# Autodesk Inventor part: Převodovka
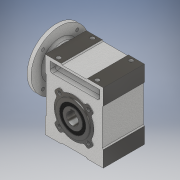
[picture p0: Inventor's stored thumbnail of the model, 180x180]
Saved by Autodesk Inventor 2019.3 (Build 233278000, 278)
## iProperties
Created: 2019-02
Part Number: Převodovka
Material: Hliník 6061-AHC
Document SubType Name: Modeling
Designer: B-hon
Density: 2.7 g/cm^3
Appearance: Hliník – litý
Author: B-hon
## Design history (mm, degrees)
sketch "Náčrt1"
  geometry: L1 (-60, 84)-(60, -60); L2 (60, 84)-(-60, -60); L3 (-27, -58)-(27, -58); L4 (-27, 82)-(27, 82); L5 (-27, 82)-(-27, 84); L6 (27, 82)-(27, 84); L7 (-27, -58)-(-27, -60); L8 (27, -58)-(27, -60); L9 (60, -60)-(27, -60); L10 (-27, -60)-(-60, -60); L11 (-60, 84)-(-27, 84); L12 (27, 84)-(60, 84); L13 (-58, 51)-(-58, -27); L14 (-58, 51)-(-60, 51); L15 (-58, -27)-(-60, -27); L16 (-60, -60)-(-60, -27); L17 (-60, 51)-(-60, 84); L18 (58, 51)-(58, -27); L19 (58, 51)-(60, 51); L20 (58, -27)-(60, -27); L21 (60, 84)-(60, 51); L22 (60, -27)-(60, -60); L23 (-4, 15.8)-(4, 15.8); L24 (-4, 15.8)-(-4, 11.843); L25 (4, 15.8)-(4, 11.843); A1 r 12.5 centre (0, 0) between (-4, 11.843) and (4, 11.843); 10 further points
  constraints: 50 end point, 10 parallel, 10 perpendicular, 7 midpoint, 6 horizontal, 4 vertical, 4 vertical alignment, 2 horizontal alignment, 2 point on circle, 2 point on line, 1 centre point, 1 coincident
  dimensions: "d0" = 144 distance of L2.end L1.start; "d1" = 120 distance of L1.end L2.end; "d2" = 25 diameter of A1; "d4" = 54 distance of L3.start L3.end; "d6" = 54 distance of L4.start L4.end; "d8" = 78 distance of L13.start L13.end; "d10" = 78 distance of L18.start L18.end; "d12" = 8 distance of L23.start L23.end; "d13" = 15.8 distance from line of point (0, 0) L23
extrude "Vysunutí1" new body sketch "Náčrt1" stored distance "d14" = 85; taper "d15" = 0 deg
sketch "Náčrt2"
  geometry: L1 (4, 15.8)-(4, 11.843) reference; L2 (-4, 15.8)-(4, 15.8) reference; L3 (-4, 11.843)-(-4, 15.8) reference; C1 r 35 at (0, 0); A1 r 12.5 centre (0, 0) between (-4, 11.843) and (4, 11.843) reference; 1 further point
  constraints: 1 centre point, 1 coincident
  dimensions: "d16" = 70 diameter of C1
extrude "Vysunutí2" join sketch "Náčrt2" distance "d18" = 3.5; taper "d19" = 0 deg
sketch "Náčrt3"
  geometry: C1 r 27.5 at (0, 0); C2 r 20 at (0, 0); 1 further point
  constraints: 2 centre point, 2 coincident
  dimensions: "d20" = 55 diameter of C1; "d21" = 40 diameter of C2
extrude "Vysunutí3" cut sketch "Náčrt3" distance "d22" = 1; taper "d23" = 0 deg
sketch "Náčrt4" dims "d29" = 85
  geometry: L1 (21.739, 34.467)-(28.234, 40.962); L2 (34.467, 21.739)-(40.962, 28.234); L3 (27, 82)-(-27, 82) reference; L4 (0, 40.75)-(0, 35); L5 (35, 0)-(40.75, 0); C1 r 3 at (30.052, 30.052); A1 r 35 centre (0, 0) between (35, 0) and (0, 35); A2 r 49.75 centre (0, 0) between (40.962, 28.234) and (28.234, 40.962); A3 r 35 centre (0, 0) between (0, 35) and (35, 0) reference; A4 r 40.75 centre (0, 0) between (40.75, 0) and (34.467, 21.739); A5 r 40.75 centre (0, 0) between (21.739, 34.467) and (0, 40.75); 2 further points
  constraints: 9 point on circle, 8 end point, 5 centre point, 4 coincident, 1 parallel, 1 vertical, 3 other
  dimensions: "d25" = 99.5 diameter of A2; "d26" = 45 deg angle of L3 L1; "d27" = 18 distance between parallel lines of L2 L1; "d28" = 9 distance from line of point (0, 0) L1; "d30" = 6 diameter of C1; "d31" = 9 distance from line of C1.centre L1
extrude "Vysunutí4" join sketch "Náčrt4" distance "d33" = 1; taper "d34" = 0 deg
fillet "Zaoblení1" dims "d35" = 5
pattern_circular "Kruhové pole1" dims angle "d37" = 360 deg
chamfer "Zkosení1" distance "d39" = 2; stored, may be unused: second distance "d40" = 2, angle "d41" = 45 deg
sketch "Náčrt5"
  geometry: C1 r 3 at (-30.052, 30.052) reference; C2 r 3 at (30.052, 30.052) reference; C3 r 3 at (30.052, -30.052) reference; C4 r 3 at (-30.052, -30.052) reference; 5 further points
  constraints: 4 coincident
hole "Díra1" sketch "Náčrt5" at (-30.052, 30.052), (30.052, 30.052), (30.052, -30.052), (-30.052, -30.052) diameter "d42" = 6.647; stored, may be unused: countersink angle "d46" = 90 deg, drill point angle "d48" = 118 deg; dims "d43" = 16, "d44" = 8, "d45" = 2, "d47" = 22.2
mirror "Zrcadlit1"
fillet "Zaoblení2" dims "d49" = 5
mirror "Zrcadlit2"
sketch "Náčrt6"
  geometry: C1 r 3 at (-30.052, 30.052) reference; C2 r 3 at (30.052, 30.052) reference; C3 r 3 at (30.052, -30.052) reference; C4 r 3 at (-30.052, -30.052) reference; 5 further points
  constraints: 4 coincident
hole "Díra2" sketch "Náčrt6" at (-30.052, 30.052), (30.052, 30.052), (30.052, -30.052), (-30.052, -30.052) diameter "d50" = 6.647; stored, may be unused: countersink angle "d54" = 90 deg, drill point angle "d56" = 118 deg; dims "d51" = 16, "d52" = 8, "d53" = 2, "d55" = 22.2
sketch "Náčrt7"
  geometry: L1 (0, 0)-(85, 0) reference; C1 r 33.5 at (42.5, -36.5); 1 further point
  constraints: 1 centre point, 1 vertical alignment
  dimensions: "d57" = 67 diameter of C1; "d58" = 36.5 distance from line of C1.centre L1
extrude "Vysunutí5" join sketch "Náčrt7" distance "d59" = 4; taper "d61" = 0 deg; dims "d60" = 2, "d62" = 0
node "Pracovní rovina1"
sketch "Náčrt8"
  geometry: C1 r 34.7 at (0, 0); 1 further point
  constraints: 1 centre point
  dimensions: "d64" = 69.4 diameter of C1
sketch "Náčrt9"
  geometry: C1 r 33.5 at (0, 0) reference; 1 further point
  node "Promítnutá smyčka1"
feature "Šablonování1" dims "d65" = 0, "d66" = 90 deg, "d67" = 0, "d68" = 90 deg
  node "Hrany1"
sketch "Náčrt10"
  geometry: C1 r 60 at (0, 0); A1 r 33.5 centre (0, 0) between (-33.466, 1.5) and (33.466, 1.5) reference; 1 further point
  constraints: 1 centre point, 1 coincident
  dimensions: "d69" = 120 diameter of C1
extrude "Vysunutí6" join sketch "Náčrt10" distance "d70" = 8; taper "d71" = 0 deg
fillet "Zaoblení3" dims "d72" = 5
sketch "Náčrt11" dims "d73" = 100
  geometry: C1 r 60 at (0, 0) reference; 3 further points
  constraints: 1 coincident, 3 other
hole "Díra3" sketch "Náčrt11" at (35.355, 35.355) diameter "d75" = 6.647; stored, may be unused: countersink angle "d79" = 90 deg, drill point angle "d81" = 118 deg; dims "d76" = 10, "d77" = 8, "d78" = 2, "d80" = 15
pattern_circular "Kruhové pole2" dims angle "d83" = 360 deg
sketch "Náčrt12"
  geometry: L1 (-53, 77)-(50, 77); L2 (50, 77)-(50, 57); L3 (50, 57)-(-53, 57); L4 (-53, 57)-(-53, 77); L5 (60, 84)-(27, 84) reference; L6 (60, 51)-(60, 84) reference; L7 (-60, 84)-(-60, 51) reference; 1 further point
  constraints: 8 end point, 2 parallel, 1 horizontal, 1 perpendicular
  dimensions: "d85" = 7 distance between parallel lines of L1 L5; "d86" = 10 distance between parallel lines of L6 L2; "d87" = 7 distance between parallel lines of L7 L4; "d88" = 20 distance of L3.end L1.start
extrude "Vysunutí7" cut sketch "Náčrt12" distance "d89" = 20; taper "d90" = 0 deg
fillet "Zaoblení4" dims "d91" = 10
fillet "Zaoblení5" dims "d92" = 5
fillet "Zaoblení6" dims "d93" = 5
mirror "Zrcadlit3"
sketch "Náčrt13"
  geometry: L1 (-100, 77.5)-(-20, 77.5); L2 (-20, 77.5)-(-20, 7.5); L3 (-20, 7.5)-(-100, 7.5); L4 (-100, 7.5)-(-100, 77.5); L5 (-33, 85)-(0, 85) reference; L6 (0, 0)-(0, 85) reference; 5 further points
  constraints: 8 end point, 4 coincident, 2 parallel, 1 horizontal, 1 perpendicular
  dimensions: "d94" = 70 distance of L1.end L2.end; "d95" = 7.5 distance between parallel lines of L1 L5; "d96" = 80 distance of L1.start L1.end; "d97" = 20 distance between parallel lines of L6 L2
hole "Díra4" sketch "Náčrt13" at (-100, 77.5), (-20, 77.5), (-20, 7.5), (-100, 7.5) diameter "d98" = 8.5; stored, may be unused: countersink angle "d102" = 90 deg, drill point angle "d104" = 118 deg; dims "d99" = 10, "d100" = 8, "d101" = 2, "d103" = 10
sketch "Náčrt14"
  geometry: C1 r 40 at (0, 0); 1 further point
  constraints: 1 centre point
  dimensions: "d105" = 80 diameter of C1
extrude "Vysunutí8" cut sketch "Náčrt14" distance "d106" = 2; taper "d107" = 0 deg
sketch "Náčrt15"
  geometry: L1 (-12, 3)-(-12, -3); L2 (-12, 3)-(-9.014, 3); L3 (42.5, 1.5)-(-42.5, 1.5) reference; L4 (-12, -3)-(-9.014, -3); C1 r 60 at (0, 0) reference; A1 r 9.5 centre (0, 0) between (-9.014, -3) and (-9.381, 1.5); 2 further points
  constraints: 6 end point, 3 point on circle, 1 centre point, 1 coincident, 1 horizontal, 1 horizontal alignment, 1 midpoint, 1 parallel, 1 point on line, 1 vertical
  dimensions: "d108" = 19 diameter of A1; "d109" = 6 distance of L1.start L1.end; "d110" = 12 distance from line of A1.centre L1
extrude "Vysunutí9" cut sketch "Náčrt15" distance "d111" = 50; taper "d112" = 0 deg
sketch "Náčrt16"
  geometry: C1 r 60 at (0, 0) reference; C2 r 15 at (0, 0); C3 r 19.5 at (0, 0); 1 further point
  constraints: 2 centre point, 2 coincident
  dimensions: "d113" = 30 diameter of C2; "d114" = 39 diameter of C3
extrude "Vysunutí10" cut sketch "Náčrt16" distance "d115" = 1; taper "d116" = 0 deg
node "Těleso1"
other parameters: "d3" = 84, "d5" = 2, "d7" = 2, "d9" = 2, "d11" = 2, "d32" = 81.5, "d63" = 8
